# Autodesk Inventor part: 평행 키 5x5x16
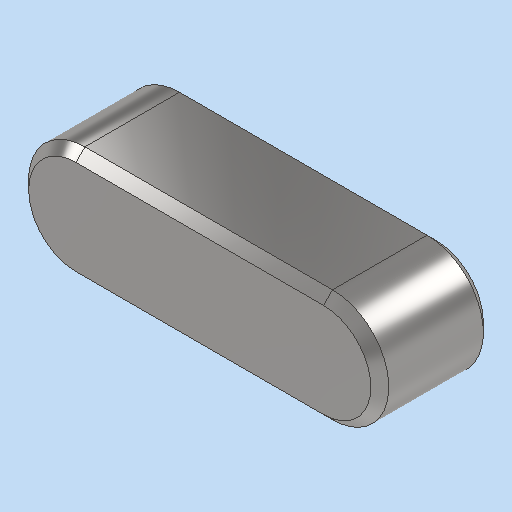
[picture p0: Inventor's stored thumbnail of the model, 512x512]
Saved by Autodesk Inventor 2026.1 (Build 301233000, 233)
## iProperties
Created: 2026-01
Part Number: 평행 키 5x5x16
Material: 강철, 연강
Description: 키 및 해당 키홈
Document SubType Name: Modeling
Designer: PC-30
Density: 7.85 g/cm^3
Appearance: 기본값
Author: jhkim
Sending System: Autodesk Inventor 2026
Preprocessor: ST-DEVELOPER v20.1
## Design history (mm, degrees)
feature "Solid1"
node "솔리드1"
